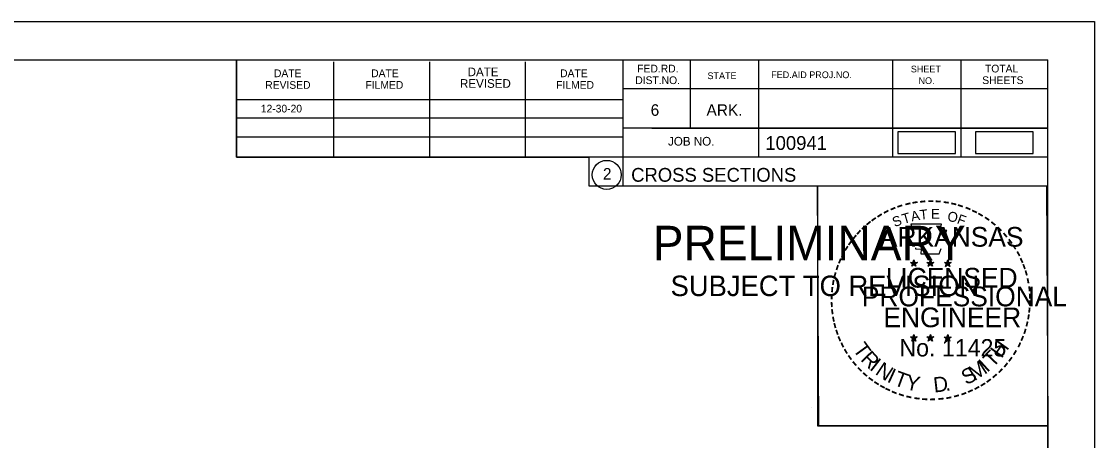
# Model space of a CAD drawing. Extents: x 1370538 to 1372872, y 376220 to 381127.
# Drawn here: x 1370762.7 to 1370871.5, y 377031.3 to 377073.8 of the extents above; entities that cross this region are included whole.
import ezdxf

# ---------------------------------------------------------------- set-up
doc = ezdxf.new("R2010")
doc.units = 0
for name, color, linetype in [('Default', 7, 'Continuous'), ('R_Border Notes', 7, 'Continuous'), ('R_No Plot', 7, 'Continuous'), ('T_Indications', 7, 'Continuous'), ('T_Notes', 7, 'Continuous')]:
    doc.layers.add(name, color=color, linetype=linetype)

msp = doc.modelspace()

# ---------------------------------------------------------------- linework, layer by layer
at = {"layer": 'Default'}
for points in [[(1370851.6, 377060.39), (1370857.43, 377060.39), (1370857.43, 377062.57), (1370851.6, 377062.57)], [(1370859.47, 377060.39), (1370865.3, 377060.39), (1370865.3, 377062.57), (1370859.47, 377062.57)]]:
    msp.add_lwpolyline(points, close=True, dxfattribs=at)
at = {"layer": 'R_Border Notes'}
for p, q in [((1370550.61, 377069.89), (1370866.79, 377069.89)), ((1370784.53, 377060.01), (1370784.53, 377069.89)), ((1370794.39, 377060.01), (1370794.39, 377069.69)), ((1370804.15, 377060.01), (1370804.15, 377069.69)), ((1370813.83, 377060.01), (1370813.83, 377069.69)), ((1370823.69, 377069.89), (1370823.69, 377057.09)), ((1370830.53, 377069.89), (1370830.53, 377062.95)), ((1370837.47, 377069.89), (1370837.47, 377060.01)), ((1370851.05, 377069.89), (1370851.05, 377060.01)), ((1370857.99, 377069.89), (1370857.99, 377060.01)), ((1370866.79, 376864.43), (1370866.79, 377069.89)), ((1370866.79, 377066.95), (1370823.69, 377066.95)), ((1370866.79, 377066.97), (1370866.79, 377066.97)), ((1370784.53, 377065.87), (1370823.69, 377065.87)), ((1370784.53, 377064.01), (1370823.69, 377064.01)), ((1370866.79, 377062.95), (1370823.69, 377062.95)), ((1370826.65, 377062.95), (1370866.79, 377062.95)), ((1370784.53, 377060.01), (1370784.53, 377062.07)), ((1370784.53, 377062.07), (1370823.69, 377062.07)), ((1370866.79, 377060.01), (1370784.53, 377060.01)), ((1370823.69, 377057.09), (1370866.79, 377057.09))]:
    msp.add_line(p, q, dxfattribs=at)
msp.add_circle((1370822.07, 377058.22), 1.47, dxfattribs=at)
at = {"layer": 'R_No Plot'}
for p, q in [((1370538.21, 377073.78), (1370871.54, 377073.78)), ((1370842.82, 377034.63), (1370842.82, 377034.63))]:
    msp.add_line(p, q, dxfattribs=at)
for points in [[(1370538.2, 377073.78), (1370871.54, 377073.78), (1370871.54, 376860.45), (1370538.2, 376860.45)], [(1370784.53, 377069.89), (1370784.53, 377060.01), (1370820.26, 377060.01), (1370820.26, 377057.09), (1370843.46, 377057.09), (1370843.46, 377032.76), (1370866.79, 377032.76), (1370866.79, 376864.43), (1370550.61, 376864.43), (1370550.61, 377069.89)], [(1370843.46, 377057.09), (1370866.67, 377057.09), (1370866.79, 377032.76), (1370843.58, 377032.76)]]:
    msp.add_lwpolyline(points, close=True, dxfattribs=at)
at = {"layer": 'T_Indications'}
for p, q in [((1370853.22, 377049.6), (1370853.18, 377049.35)), ((1370853.22, 377049.23), (1370853.22, 377049.6)), ((1370853.22, 377049.6), (1370853.27, 377049.35)), ((1370854.89, 377049.6), (1370854.85, 377049.35)), ((1370854.89, 377049.23), (1370854.89, 377049.6)), ((1370854.89, 377049.6), (1370854.94, 377049.35)), ((1370856.65, 377049.59), (1370856.61, 377049.33)), ((1370856.65, 377049.22), (1370856.65, 377049.59)), ((1370856.65, 377049.59), (1370856.7, 377049.34)), ((1370852.87, 377049.34), (1370853.22, 377049.23)), ((1370852.87, 377049.34), (1370853.12, 377049.3)), ((1370852.87, 377049.34), (1370853.11, 377049.22)), ((1370853, 377048.94), (1370853.22, 377049.23)), ((1370853, 377048.94), (1370853.13, 377049.18)), ((1370853, 377048.94), (1370853.22, 377049.15)), ((1370853.57, 377049.34), (1370853.22, 377049.23)), ((1370853.43, 377048.94), (1370853.22, 377049.23)), ((1370853.43, 377048.94), (1370853.22, 377049.15)), ((1370853.57, 377049.34), (1370853.28, 377049.29)), ((1370853.43, 377048.94), (1370853.3, 377049.23)), ((1370853.57, 377049.34), (1370853.36, 377049.24)), ((1370854.54, 377049.34), (1370854.89, 377049.23)), ((1370854.54, 377049.34), (1370854.79, 377049.3)), ((1370854.54, 377049.34), (1370854.78, 377049.22)), ((1370854.67, 377048.94), (1370854.89, 377049.23)), ((1370854.67, 377048.94), (1370854.8, 377049.18)), ((1370854.67, 377048.94), (1370854.89, 377049.15)), ((1370855.24, 377049.34), (1370854.89, 377049.23)), ((1370855.1, 377048.94), (1370854.89, 377049.23)), ((1370855.1, 377048.94), (1370854.89, 377049.15)), ((1370855.24, 377049.34), (1370854.95, 377049.29)), ((1370855.1, 377048.94), (1370854.97, 377049.23)), ((1370855.24, 377049.34), (1370855.03, 377049.24)), ((1370856.31, 377049.33), (1370856.65, 377049.22)), ((1370856.31, 377049.33), (1370856.56, 377049.29)), ((1370856.31, 377049.33), (1370856.54, 377049.21)), ((1370856.44, 377048.92), (1370856.65, 377049.22)), ((1370856.44, 377048.92), (1370856.56, 377049.17)), ((1370856.44, 377048.92), (1370856.65, 377049.14)), ((1370857, 377049.33), (1370856.65, 377049.22)), ((1370856.87, 377048.92), (1370856.65, 377049.22)), ((1370856.87, 377048.92), (1370856.65, 377049.14)), ((1370857, 377049.33), (1370856.72, 377049.28)), ((1370856.87, 377048.92), (1370856.73, 377049.21)), ((1370857, 377049.33), (1370856.8, 377049.23)), ((1370853.22, 377042.02), (1370853.18, 377041.77)), ((1370853.22, 377041.66), (1370853.22, 377042.02)), ((1370853.22, 377042.02), (1370853.27, 377041.77)), ((1370854.89, 377042.02), (1370854.84, 377041.77)), ((1370854.89, 377041.66), (1370854.89, 377042.02)), ((1370854.89, 377042.02), (1370854.93, 377041.77)), ((1370856.65, 377042.01), (1370856.61, 377041.76)), ((1370856.65, 377041.65), (1370856.65, 377042.01)), ((1370856.65, 377042.01), (1370856.7, 377041.76)), ((1370852.87, 377041.77), (1370853.22, 377041.66)), ((1370852.87, 377041.77), (1370853.12, 377041.73)), ((1370852.87, 377041.77), (1370853.1, 377041.65)), ((1370853, 377041.36), (1370853.22, 377041.66)), ((1370853, 377041.36), (1370853.13, 377041.61)), ((1370853, 377041.36), (1370853.21, 377041.58)), ((1370853.43, 377041.36), (1370853.21, 377041.58)), ((1370853.56, 377041.77), (1370853.22, 377041.66)), ((1370853.43, 377041.36), (1370853.22, 377041.66)), ((1370853.56, 377041.77), (1370853.28, 377041.72)), ((1370853.43, 377041.36), (1370853.29, 377041.65)), ((1370853.56, 377041.77), (1370853.36, 377041.67)), ((1370854.54, 377041.77), (1370854.89, 377041.66)), ((1370854.54, 377041.77), (1370854.79, 377041.73)), ((1370854.54, 377041.77), (1370854.77, 377041.65)), ((1370854.67, 377041.36), (1370854.89, 377041.66)), ((1370854.67, 377041.36), (1370854.8, 377041.61)), ((1370854.67, 377041.36), (1370854.88, 377041.58)), ((1370855.1, 377041.36), (1370854.88, 377041.58)), ((1370855.23, 377041.77), (1370854.89, 377041.66)), ((1370855.1, 377041.36), (1370854.89, 377041.66)), ((1370855.23, 377041.77), (1370854.95, 377041.72)), ((1370855.1, 377041.36), (1370854.96, 377041.65)), ((1370855.23, 377041.77), (1370855.03, 377041.67)), ((1370856.3, 377041.76), (1370856.65, 377041.65)), ((1370856.3, 377041.76), (1370856.56, 377041.72)), ((1370856.3, 377041.76), (1370856.54, 377041.64)), ((1370856.44, 377041.35), (1370856.65, 377041.65)), ((1370856.44, 377041.35), (1370856.56, 377041.6)), ((1370856.44, 377041.35), (1370856.65, 377041.57)), ((1370857, 377041.76), (1370856.65, 377041.65)), ((1370856.87, 377041.35), (1370856.65, 377041.65)), ((1370856.87, 377041.35), (1370856.65, 377041.57)), ((1370857, 377041.76), (1370856.71, 377041.71)), ((1370856.87, 377041.35), (1370856.73, 377041.64)), ((1370857, 377041.76), (1370856.8, 377041.66))]:
    msp.add_line(p, q, dxfattribs=at)
for points in [[(1370852.91, 377053.22), (1370853.18, 377052.39)], [(1370856.42, 377052.3), (1370856.57, 377052.58), (1370855.88, 377052.56), (1370856.03, 377053.22), (1370852.91, 377053.22)], [(1370853.4, 377050.8), (1370853.4, 377050.71), (1370853.97, 377050.69), (1370853.91, 377050.22), (1370855.78, 377050.22), (1370855.98, 377050.76)], [(1370853.22, 377049.6), (1370853.43, 377048.94), (1370852.87, 377049.34), (1370853.57, 377049.34), (1370853, 377048.94), (1370853.22, 377049.6)], [(1370854.89, 377049.6), (1370855.1, 377048.94), (1370854.54, 377049.34), (1370855.24, 377049.34), (1370854.67, 377048.94), (1370854.89, 377049.6)], [(1370856.65, 377049.59), (1370856.87, 377048.92), (1370856.31, 377049.33), (1370857, 377049.33), (1370856.44, 377048.92), (1370856.65, 377049.59)], [(1370853.22, 377042.02), (1370853.43, 377041.36), (1370852.87, 377041.77), (1370853.56, 377041.77), (1370853, 377041.36), (1370853.22, 377042.02)], [(1370854.89, 377042.02), (1370855.1, 377041.36), (1370854.54, 377041.77), (1370855.23, 377041.77), (1370854.67, 377041.36), (1370854.89, 377042.02)], [(1370856.65, 377042.01), (1370856.87, 377041.35), (1370856.3, 377041.76), (1370857, 377041.76), (1370856.44, 377041.35), (1370856.65, 377042.01)]]:
    msp.add_lwpolyline(points, dxfattribs=at)
for centre, radius in [((1370853.22, 377049.23), 0.172), ((1370853.22, 377049.23), 0.145), ((1370853.22, 377049.23), 0.116), ((1370853.22, 377049.23), 0.0991), ((1370853.22, 377049.23), 0.0747), ((1370853.22, 377049.23), 0.0495), ((1370853.22, 377049.23), 0.0296), ((1370854.89, 377049.23), 0.172), ((1370854.89, 377049.23), 0.145), ((1370854.89, 377049.23), 0.116), ((1370854.89, 377049.23), 0.0991), ((1370854.89, 377049.23), 0.0747), ((1370854.89, 377049.23), 0.0495), ((1370854.89, 377049.23), 0.0296), ((1370856.65, 377049.22), 0.172), ((1370856.65, 377049.22), 0.145), ((1370856.65, 377049.22), 0.116), ((1370856.65, 377049.22), 0.0991), ((1370856.65, 377049.22), 0.0747), ((1370856.65, 377049.22), 0.0495), ((1370856.65, 377049.22), 0.0296), ((1370853.22, 377041.66), 0.172), ((1370854.88, 377041.66), 0.172), ((1370856.65, 377041.65), 0.172), ((1370853.22, 377041.66), 0.145), ((1370853.22, 377041.66), 0.116), ((1370853.22, 377041.66), 0.0991), ((1370853.22, 377041.66), 0.0747), ((1370853.22, 377041.66), 0.0495), ((1370853.22, 377041.66), 0.0296), ((1370854.88, 377041.66), 0.145), ((1370854.88, 377041.66), 0.116), ((1370854.88, 377041.66), 0.0991), ((1370854.88, 377041.66), 0.0747), ((1370854.88, 377041.66), 0.0495), ((1370854.88, 377041.66), 0.0296), ((1370856.65, 377041.65), 0.145), ((1370856.65, 377041.65), 0.116), ((1370856.65, 377041.65), 0.0991), ((1370856.65, 377041.65), 0.0747), ((1370856.65, 377041.65), 0.0495), ((1370856.65, 377041.65), 0.0296)]:
    msp.add_circle(centre, radius, dxfattribs=at)

# ---------------------------------------------------------------- texts
at = {"layer": 'R_Border Notes'}
for s, height, p in [('DATE', 0.879, (1370807.97, 377068.23)), ('FED.RD.', 0.782, (1370825.17, 377068.61)), ('SHEET', 0.684, (1370852.91, 377068.61)), ('TOTAL', 0.782, (1370860.43, 377068.61)), ('DATE', 0.782, (1370788.33, 377068.13)), ('DATE', 0.782, (1370798.19, 377068.13)), ('REVISED', 0.879, (1370807.19, 377067.05)), ('DATE', 0.782, (1370817.35, 377068.13)), ('DIST.NO.', 0.782, (1370824.97, 377067.43)), ('STATE', 0.684, (1370832.29, 377067.93)), ('FED.AID PROJ.NO.', 0.684, (1370838.75, 377068.03)), ('NO.', 0.684, (1370853.69, 377067.43)), ('SHEETS', 0.782, (1370860.15, 377067.43)), ('REVISED', 0.782, (1370787.45, 377066.95)), ('FILMED', 0.782, (1370797.61, 377066.95)), ('FILMED', 0.782, (1370816.95, 377066.95)), ('6', 1.17, (1370826.53, 377064.21)), ('ARK.', 1.172, (1370832.19, 377064.21)), ('JOB NO.', 0.879, (1370828.29, 377061.19)), ('100941', 1.4, (1370838.16, 377060.75)), ('2', 1.17, (1370821.69, 377057.74)), ('CROSS SECTIONS', 1.4, (1370824.55, 377057.52))]:
    msp.add_text(s, height=height, rotation=360, dxfattribs=at).set_placement(p)
msp.add_text('12-30-20', height=0.78, dxfattribs=at).set_placement((1370787, 377064.55))
at = {"layer": 'T_Indications'}
for s, height, rotation, p in [('-', 1.6, 24.3072, (1370851.03, 377054.08)), ('-', 1.6, 19.1761, (1370851.66, 377054.35)), ('-', 1.6, 13.6301, (1370852.41, 377054.59)), ('-', 1.6, 10.2193, (1370853.09, 377054.75)), ('-', 1.6, 5.8968, (1370853.82, 377054.86)), ('-', 1.6, 0.1862, (1370854.59, 377054.93)), ('-', 1.6, 357.743, (1370855.31, 377054.92)), ('-', 1.6, 352.1617, (1370856.06, 377054.86)), ('-', 1.6, 347.2049, (1370856.78, 377054.75)), ('-', 1.6, 342.3362, (1370857.41, 377054.6)), ('-', 1.6, 337.8551, (1370858.15, 377054.37)), ('-', 1.6, 36.2317, (1370849.22, 377053)), ('-', 1.6, 34.0636, (1370849.8, 377053.39)), ('-', 1.6, 28.7918, (1370850.39, 377053.76)), ('S', 1, 21.594, (1370851.27, 377052.9)), ('T', 1, 16.4036, (1370852.18, 377053.23)), ('A', 1, 11.2132, (1370853.01, 377053.48)), ('T', 1, 6.0228, (1370853.86, 377053.65)), ('E', 1, 0.8323, (1370854.96, 377053.76)), ('O', 1, 350.4515, (1370856.57, 377053.55)), ('F', 1, 340.0707, (1370857.52, 377053.32)), ('-', 1.6, 334.1211, (1370858.78, 377054.1)), ('-', 1.6, 329.6409, (1370859.36, 377053.82)), ('-', 1.6, 325.8627, (1370860, 377053.46)), ('-', 1.6, 42.9622, (1370848.31, 377052.2)), ('-', 1.6, 38.9507, (1370848.74, 377052.62)), ('ARKANSAS', 2, 360, (1370849.77, 377050.93)), ('-', 1.6, 320.5297, (1370860.61, 377053.03)), ('-', 1.6, 315.5786, (1370861.21, 377052.54)), ('-', 1.6, 50.6142, (1370847.46, 377051.24)), ('-', 1.6, 48.423, (1370847.86, 377051.72)), ('-', 1.6, 309.8797, (1370861.78, 377051.99)), ('-', 1.6, 306.6522, (1370862.3, 377051.39)), ('-', 1.6, 58.0706, (1370846.72, 377050.14)), ('-', 1.6, 54.2325, (1370847.05, 377050.67)), ('-', 1.4, 303.6753, (1370862.79, 377050.82)), ('-', 1.6, 67.7743, (1370846.15, 377048.92)), ('-', 1.6, 62.8713, (1370846.41, 377049.53)), ('-', 1.6, 299.6684, (1370863.11, 377050.22)), ('-', 1.6, 294.6628, (1370863.43, 377049.6)), ('-', 1.6, 75.461, (1370845.73, 377047.58)), ('-', 1.6, 72.3945, (1370845.93, 377048.29)), ('LICENSED', 2, 360, (1370850.36, 377046.78)), ('DWB', 0.01, 360, (1370853.21, 377049.23)), ('DWB', 0.01, 360, (1370854.88, 377049.23)), ('DWB', 0.01, 360, (1370856.64, 377049.22)), ('-', 1.6, 290.5728, (1370863.69, 377049.03)), ('-', 1.6, 285.1233, (1370863.92, 377048.45)), ('-', 1.6, 81.2013, (1370845.6, 377046.86)), ('-', 1.6, 280.5493, (1370864.12, 377047.71)), ('-', 1.6, 85.1863, (1370845.52, 377046.17)), ('PROFESSIONAL', 2, 360, (1370847.94, 377044.88)), ('-', 1.6, 276.5962, (1370864.28, 377046.94)), ('-', 1.6, 274.3301, (1370864.34, 377046.22)), ('-', 1.6, 94.1959, (1370845.53, 377044.75)), ('-', 1.6, 89.0622, (1370845.5, 377045.47)), ('-', 1.6, 269.9407, (1370864.38, 377045.58)), ('-', 1.6, 98.9479, (1370845.61, 377044.08)), ('ENGINEER', 2, 360, (1370850.13, 377042.76)), ('-', 1.6, 260.9953, (1370864.29, 377044.26)), ('-', 1.6, 263.5172, (1370864.36, 377044.92)), ('-', 1.6, 101.7149, (1370845.74, 377043.35)), ('-', 1.6, 105.4578, (1370845.9, 377042.75)), ('-', 1.6, 255.7626, (1370864.18, 377043.59)), ('-', 1.6, 109.0874, (1370846.12, 377042.12)), ('-', 1.6, 114.0643, (1370846.37, 377041.52)), ('-', 1.6, 247.8887, (1370863.77, 377042.19)), ('-', 1.6, 252.8681, (1370864, 377042.87)), ('-', 1.6, 115.7289, (1370846.68, 377040.91)), ('T', 1.54, 306.0406, (1370846.98, 377040.5)), ('No. 11425', 1.757, 360, (1370851.75, 377039.8)), ('DWB', 0.01, 360, (1370853.2, 377041.65)), ('DWB', 0.01, 360, (1370854.87, 377041.65)), ('DWB', 0.01, 360, (1370856.64, 377041.64)), ('H', 1.54, 54.6088, (1370862.1, 377039.53)), ('-', 1.6, 244.6197, (1370863.51, 377041.56)), ('-', 1.6, 120.4471, (1370847.03, 377040.32)), ('-', 1.6, 125.8934, (1370847.44, 377039.76)), ('R', 1.54, 314.005, (1370847.74, 377039.45)), ('T', 1.54, 46.6444, (1370861.21, 377038.59)), ('-', 1.6, 233.8452, (1370862.72, 377040.16)), ('-', 1.6, 239.0712, (1370863.12, 377040.81)), ('-', 1.6, 130.7181, (1370847.9, 377039.21)), ('-', 1.6, 134.2238, (1370848.42, 377038.66)), ('I', 1.54, 321.9694, (1370848.64, 377038.52)), ('N', 1.54, 326.5002, (1370849.21, 377038.05)), ('I', 1.54, 335.3603, (1370850.41, 377037.26)), ('S', 1.54, 26.9312, (1370858.52, 377036.86)), ('M', 1.54, 32.6563, (1370859.36, 377037.27)), ('I', 1.54, 42.1136, (1370860.64, 377038.11)), ('-', 1.6, 225.7653, (1370861.81, 377039.03)), ('-', 1.6, 231.2538, (1370862.29, 377039.59)), ('-', 1.6, 138.9338, (1370848.94, 377038.2)), ('-', 1.6, 144.6463, (1370849.5, 377037.79)), ('T', 1.54, 339.8912, (1370851.08, 377036.93)), ('Y', 1.54, 347.8556, (1370852.29, 377036.49)), ('D', 1.54, 6.3969, (1370855.28, 377036.13)), ('-', 1.6, 215.7363, (1370860.74, 377038.05)), ('-', 1.6, 221.0851, (1370861.28, 377038.52)), ('-', 1.6, 148.0898, (1370850.06, 377037.42)), ('-', 1.6, 151.5704, (1370850.64, 377037.1)), ('-', 1.6, 154.6002, (1370851.16, 377036.85)), ('.', 1.54, 13.7642, (1370856.47, 377036.26)), ('-', 1.6, 204.2516, (1370859.02, 377037)), ('-', 1.6, 207.3568, (1370859.64, 377037.31)), ('-', 1.6, 212.2491, (1370860.2, 377037.66)), ('-', 1.6, 158.5612, (1370851.78, 377036.59)), ('-', 1.6, 162.7983, (1370852.47, 377036.38)), ('-', 1.6, 167.5555, (1370853.19, 377036.22)), ('-', 1.6, 173.1155, (1370853.96, 377036.11)), ('-', 1.6, 176.5183, (1370854.71, 377036.05)), ('-', 1.6, 181.5918, (1370855.45, 377036.07)), ('-', 1.6, 185.8167, (1370856.26, 377036.15)), ('-', 1.6, 191.2858, (1370856.99, 377036.28)), ('-', 1.6, 195.4743, (1370857.72, 377036.48)), ('-', 1.6, 200.7184, (1370858.4, 377036.72))]:
    msp.add_text(s, height=height, rotation=rotation, dxfattribs=at).set_placement(p)
at = {"layer": 'T_Notes'}
for s, height, p in [('PRELIMINARY', 3.5, (1370826.74, 377049.55)), ('DWB', 0.01, (1370827.48, 377051.4)), ('SUBJECT TO REVISION', 2.0751, (1370828.55, 377045.92))]:
    msp.add_text(s, height=height, rotation=360, dxfattribs=at).set_placement(p)

doc.saveas('drawing.dxf')
